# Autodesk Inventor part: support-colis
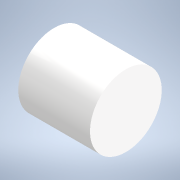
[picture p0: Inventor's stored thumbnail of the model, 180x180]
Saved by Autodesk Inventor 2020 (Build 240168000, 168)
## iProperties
Created: 2021-10
Part Number: support-colis
Material: Générique
Document SubType Name: Modeling
Designer: bruno
Density: 1 g/cm^3
Appearance: Blanche
Author: bruno
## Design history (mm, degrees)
sketch "Esquisse1"
  geometry: C1 r 15 at (0, 0); 1 further point
  constraints: 1 centre point, 1 coincident
  dimensions: "d0" = 30 diameter of C1
extrude "Extrusion1" new body sketch "Esquisse1" distance "d1" = 30; taper "d2" = 0 deg
node "Solide1"
